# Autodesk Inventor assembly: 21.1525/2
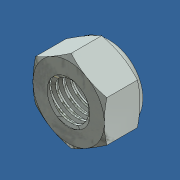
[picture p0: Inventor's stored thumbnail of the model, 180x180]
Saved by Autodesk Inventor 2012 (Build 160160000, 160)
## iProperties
Created: 2012-02
Part Number: 21.1525/2
Document SubType Name: Assembly
Designer: Administrator
Description: M6 NYLON INSERT HEX LOCKNUT
Mass: 2.52881 g
Surface Area: 6.57176 cm^2
Volume: 0.349507 cm^3
Density: 7.23538 g/cm^3
Author: Administrator
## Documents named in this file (4)
- C:\Andys Backup Data\ANDY'S INVENTOR\INVENTOR LIBRARIES\PARTS LIBRARY\FASTENING ELEMENTS\NUTS\21.1525_2 M6 NYLON INSERT HEX LOCKNUT.iam
- 21.1525/2 M6 NYLON INSERT HEX LOCKNUT.iam
- C:\Andys Backup Data\ANDY'S INVENTOR\INVENTOR LIBRARIES\PARTS LIBRARY\FASTENING ELEMENTS\NUTS\SUBCOMPONENTS\21.1525_2 M6 NYLON INSERT HEX LOCKNUT BODY.ipt
- C:\Andys Backup Data\ANDY'S INVENTOR\INVENTOR LIBRARIES\PARTS LIBRARY\FASTENING ELEMENTS\NUTS\SUBCOMPONENTS\21.1525_2 M6 NYLON INSERT HEX LOCKNUT INSERT.ipt
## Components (2 placed, 2 different names)
1. 21.1525_2 M6 NYLON INSERT HEX LOCKNUT BODY:1 — Mate:1, Flush:1
2. 21.1525_2 M6 NYLON INSERT HEX LOCKNUT INSERT:1 — Mate:1, Flush:1
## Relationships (2: Mate 1, Flush 1)
- Mate:1: 21.1525_2 M6 NYLON INSERT HEX LOCKNUT BODY:1 ↔ 21.1525_2 M6 NYLON INSERT HEX LOCKNUT INSERT:1
- Flush:1: 21.1525_2 M6 NYLON INSERT HEX LOCKNUT BODY:1 ↔ 21.1525_2 M6 NYLON INSERT HEX LOCKNUT INSERT:1
